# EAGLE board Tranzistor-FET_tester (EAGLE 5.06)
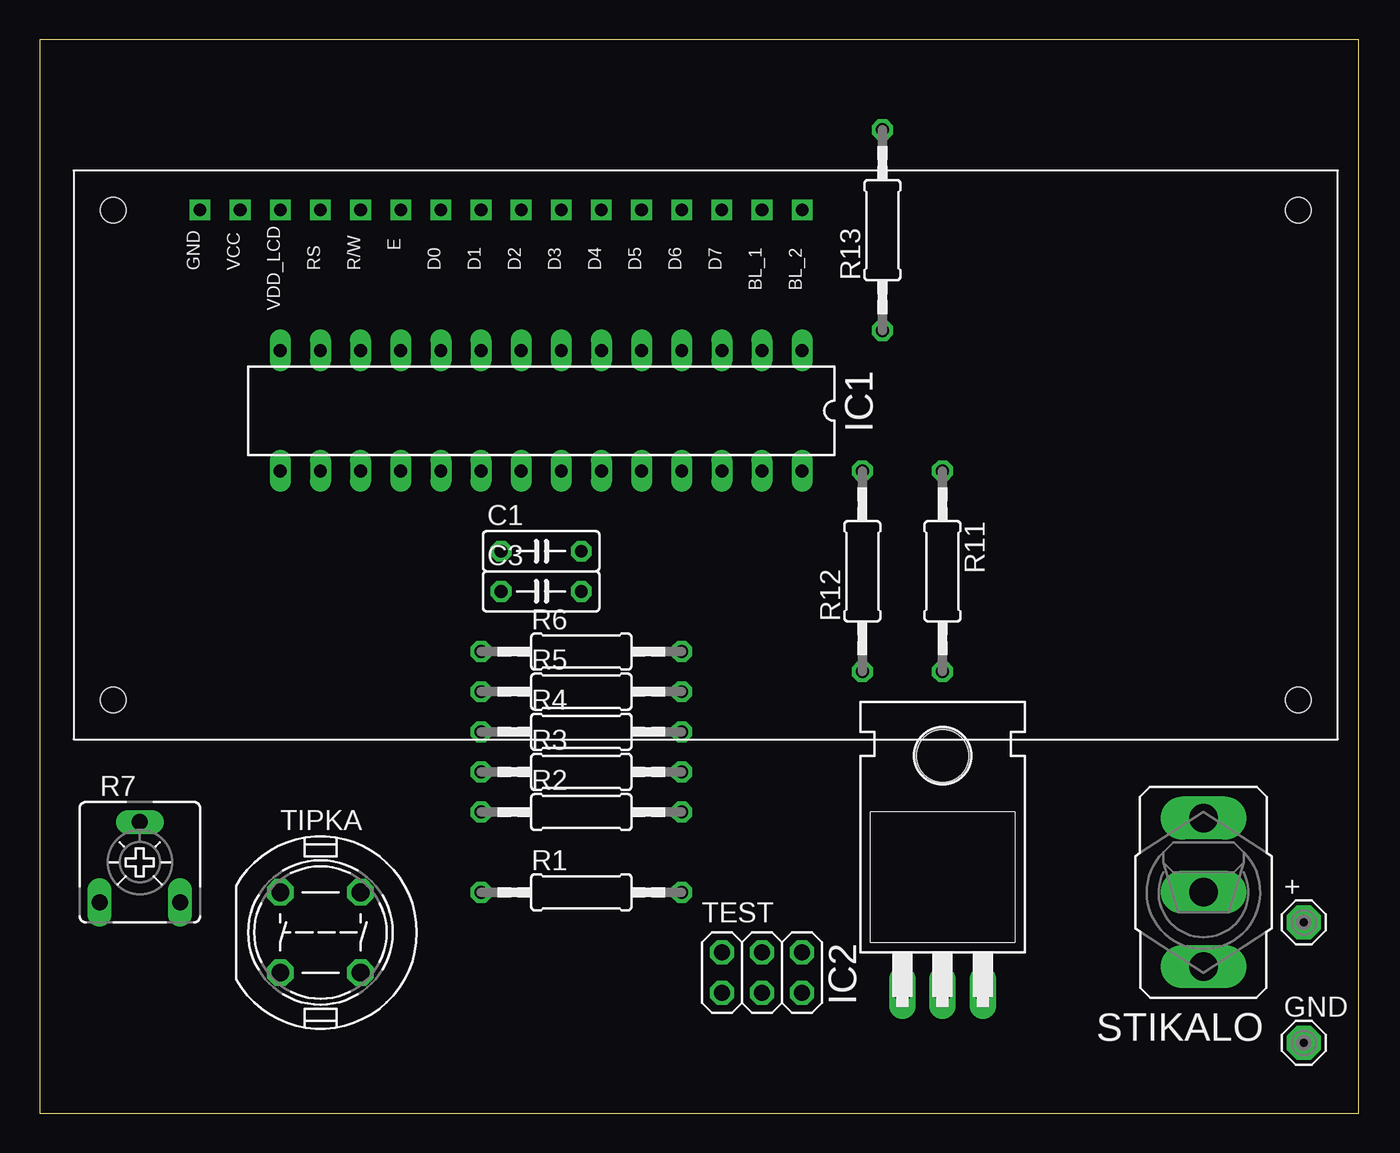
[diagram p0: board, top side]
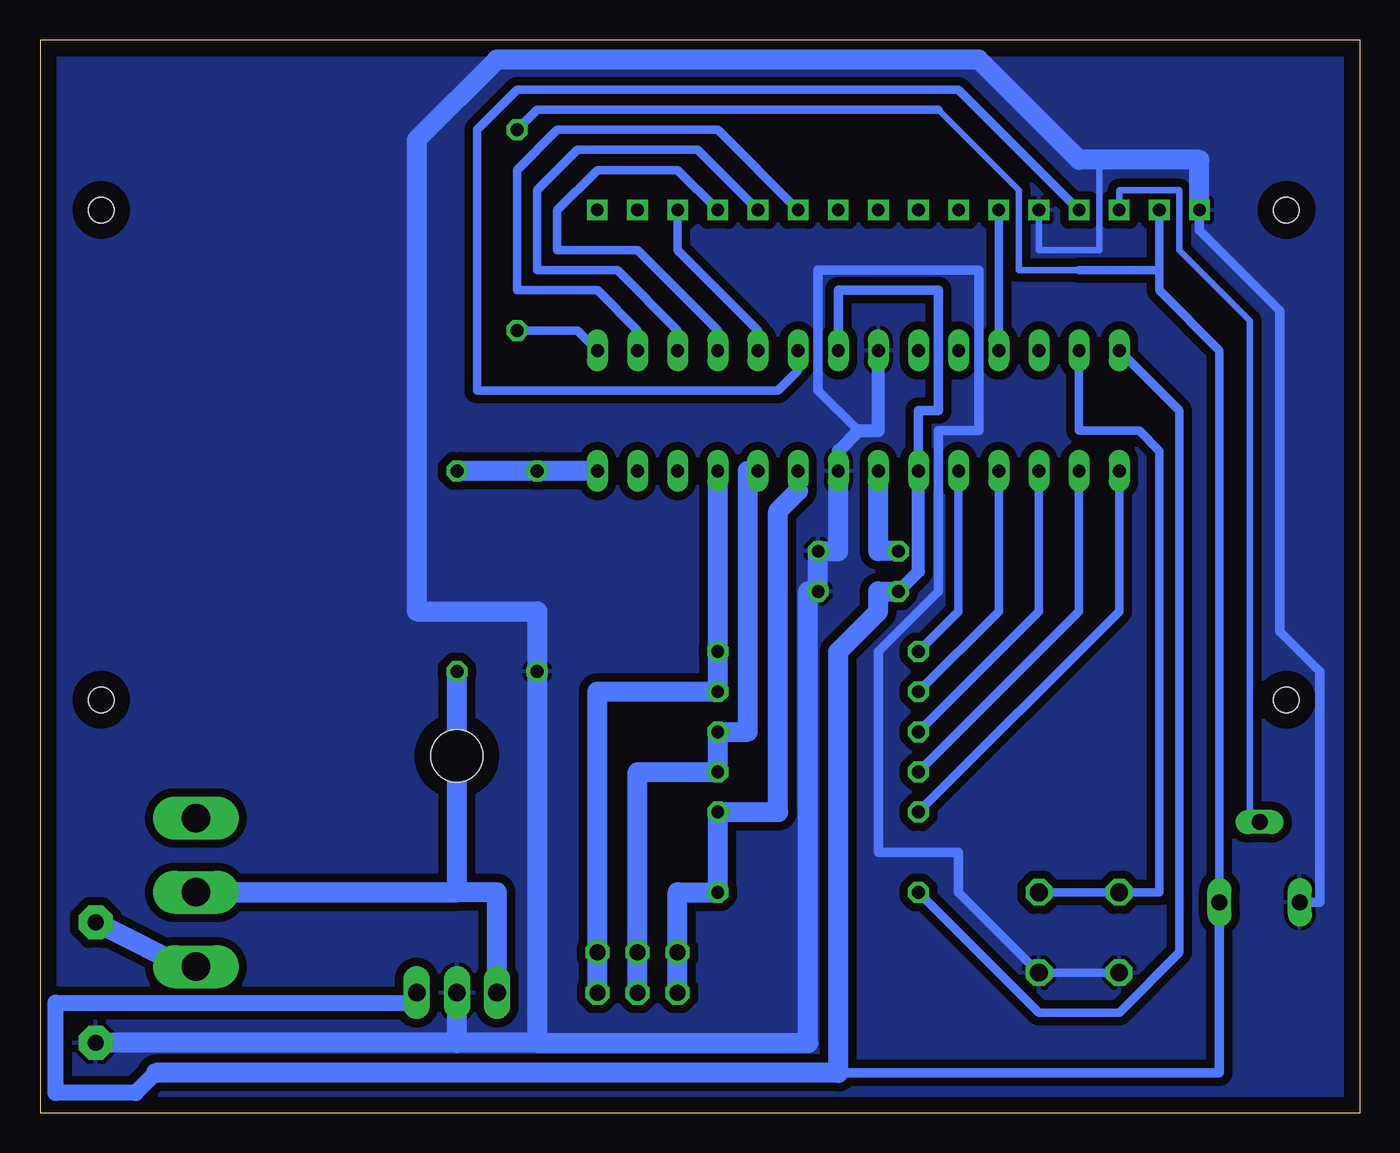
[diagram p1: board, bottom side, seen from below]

Size 83.49 x 67.94 mm. Coordinates in mm from the lower left corner, seen from the top.
Outline: 0,0 83.49,0 83.49,67.94 0,67.94 0,0
Copper layers (1*16): Top 0.035mm / dielectric 1.5mm / Bottom 0.035mm
Design rules "default *": minimum track width 21mil, minimum drill 24mil, track to track 21mil, track to pad 21mil, pad to pad 21mil, via to via 8mil, smd to smd 8mil, copper to edge 40mil, drill to drill 8mil, minimum pad ring 10mil, minimum via ring 8mil, stop-mask expansion 4mil, vias tented up to drill 0mil, thermal gap 10mil

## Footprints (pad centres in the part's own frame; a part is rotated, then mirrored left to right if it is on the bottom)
MCS10B = drill 1.016 pad 2.159 octagon: MP 0,0
C050-025X075 = drill 0.813 octagon: 1 -2.54,0; 2 2.54,0
DIL28-3 = drill 0.813 long: 1 -16.51,-3.81; 2 -13.97,-3.81; 3 -11.43,-3.81; 4 -8.89,-3.81; 5 -6.35,-3.81; 6 -3.81,-3.81; 7 -1.27,-3.81; 8 1.27,-3.81; 9 3.81,-3.81; 10 6.35,-3.81; 11 8.89,-3.81; 12 11.43,-3.81; 13 13.97,-3.81; 14 16.51,-3.81; 15 16.51,3.81; 16 13.97,3.81; 17 11.43,3.81; 18 8.89,3.81; 19 6.35,3.81; 20 3.81,3.81; 21 1.27,3.81; 22 -1.27,3.81; 23 -3.81,3.81; 24 -6.35,3.81; 25 -8.89,3.81; 26 -11.43,3.81; 27 -13.97,3.81; 28 -16.51,3.81
TO220H = drill 1.118 long: 1 -2.54,-10.16; 2 0,-10.16; 3 2.54,-10.16 | hole 3.302: 0,4.826
0207/12 = drill 0.813 octagon: 1 -6.35,0; 2 6.35,0
CA6V = drill 1.016 long: A -2.54,-2.54; E 2.54,-2.54; S 0,2.54
M9040P = drill 1.803 long: 1 0,4.699; 2 0,0; 3 0,-4.699
2X03 = drill 1.016 octagon: 1 -2.54,-1.27; 2 -2.54,1.27; 3 0,-1.27; 4 0,1.27; 5 2.54,-1.27; 6 2.54,1.27
DT6 = drill 1.118 octagon: 1 -2.54,2.54; 2 2.54,2.54; 3 2.54,-2.54; 4 -2.54,-2.54
DEM16216 = drill 0.8 square: BL_1 35.56,0; BL_2 38.1,0; D0 15.24,0; D1 17.78,0; D2 20.32,0; D3 22.86,0; D4 25.4,0; D5 27.94,0; D6 30.48,0; D7 33.02,0; E 12.7,0; GND 0,0; R/W 10.16,0; RS 7.62,0; VCC 2.54,0; VDD_LCD 5.08,0 | hole 1.6: -5.5,0; 69.5,0; -5.5,-31; 69.5,-31

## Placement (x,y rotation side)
+  MCS10B  [MCS10B]  80.01,12.07 0 top
C1  100n  [C050-025X075]  31.75,35.56 0 top
C3  100n  [C050-025X075]  31.75,33.02 0 top
GND  MCS10B  [MCS10B]  80.01,4.45 0 top
IC1  MEGA8-P  [DIL28-3]  31.75,44.45 180 top
IC2  7805T  [TO220H]  57.15,17.78 0 top
R1  680  [0207/12]  34.29,13.97 0 top
R2  470K  [0207/12]  34.29,19.05 0 top
R3  680  [0207/12]  34.29,21.59 0 top
R4  470K  [0207/12]  34.29,24.13 0 top
R5  680  [0207/12]  34.29,26.67 0 top
R6  470K  [0207/12]  34.29,29.21 0 top
R7  5K  [CA6V]  6.35,15.88 0 top
R11  10K  [0207/12]  57.15,34.29 270 top
R12  3K3  [0207/12]  52.07,34.29 90 top
R13  10K  [0207/12]  53.34,55.88 90 top
STIKALO  9450-1  [M9040P]  73.66,13.97 180 top
TEST  [2X03]  45.72,8.89 0 top
TIPKA  DT6  [DT6]  17.78,11.43 0 top
U$1  [DEM16216]  10.16,57.15 0 top

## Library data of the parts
+ GND = solpad
C1 C3 R1-R6 R11-R13 = rcl
IC1 = atmel
IC2 = linear
R7 = pot
STIKALO = switch
TEST = pinhead
TIPKA = switch-misc
U$1 = lcd

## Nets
+5V: R7.E R13.2 U$1.VCC
+9V: +.MP STIKALO.1
GND: C1.2 C3.2 GND.MP IC1.8 IC1.22 IC2.2 R7.A R12.1 TIPKA.3 TIPKA.4 U$1.GND U$1.R/W
N$1: IC1.23 R1.2 R2.2 TEST.1 TEST.2
N$2: IC1.24 R3.2 R4.2 TEST.3 TEST.4
N$3: IC1.25 R5.2 R6.2 TEST.5 TEST.6
N$4: IC1.13 TIPKA.1 TIPKA.2
N$6: R7.S U$1.VDD_LCD
N$7: IC1.28 R11.1 R12.2
N$9: IC1.14 R1.1
N$10: IC1.15 R2.1
N$11: IC1.16 R3.1
N$12: IC1.17 R4.1
N$13: IC1.18 R5.1
N$14: IC1.19 R6.1
N$15: IC1.1 R13.1
N$17: C1.1 IC1.21
N$18: C3.1 IC1.7 IC1.20 IC2.3
N$23: IC2.1 R11.2 STIKALO.2
N$24: IC1.2 U$1.D4
N$25: IC1.3 U$1.D5
N$26: IC1.4 U$1.D6
N$27: IC1.5 U$1.D7
N$28: IC1.6 U$1.RS
N$29: IC1.11 U$1.E

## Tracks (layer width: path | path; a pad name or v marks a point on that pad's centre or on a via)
+5V
  Bottom 0.406: 17.78,53.34 21.59,53.34 21.59,58.42 26.67,63.5
  Bottom 0.533: 12.7,53.34 17.78,53.34 | R13.2 52.07,63.5 26.67,63.5 | 12.7,53.34 12.7,52.07 8.89,48.26 R7.E | 12.7,53.34 U$1.VCC
+9V
  Bottom 0.533: STIKALO.1 73.66,8.89
  Bottom 1.27: 73.66,8.89 +.MP
GND
  Bottom 0.406: U$1.R/W 20.32,54.61 16.51,54.61 16.51,60.33
  Bottom 0.533: IC1.22 33.02,41.91 | TIPKA.3 TIPKA.4
  Bottom 0.61: TIPKA.3 25.4,13.97 25.4,16.51 30.48,16.51 30.48,29.21 26.67,33.02 26.67,43.18 24.13,43.18 24.13,53.34 34.29,53.34 34.29,45.72 31.75,43.18 | U$1.GND 10.16,55.88 5.08,50.8 5.08,30.48 2.54,27.94 2.54,13.34 R7.A
  Bottom 0.813: IC1.8 30.48,43.18 31.75,43.18 33.02,41.91 | 34.92,33.02 C3.2
  Bottom 1.27: U$1.GND 10.16,60.33 16.51,60.33 17.78,60.33 24.13,66.67 54.61,66.67 59.69,61.59 59.69,31.75 52.07,31.75 R12.1 52.07,4.45 | C3.2 C1.2 33.02,35.56 IC1.22 | 34.92,33.02 34.92,4.45 52.07,4.45 | 52.07,4.45 57.15,4.45 | 57.15,4.45 GND.MP | 57.15,4.45 IC2.2
  pour Bottom: 0,67.31 83.82,67.31 83.82,0 0,0 0,1.27
N$1
  Bottom 0.533: 35.56,39.37 IC1.23
  Bottom 1.27: TEST.1 TEST.2 43.18,13.97 R1.2 R2.2 36.83,19.05 36.83,38.1 35.56,39.37
N$2
  Bottom 0.813: 38.73,40.64 IC1.24
  Bottom 1.27: TEST.3 TEST.4 45.72,21.59 R3.2 R4.2 38.73,24.13 38.73,36.83 38.73,40.64
N$3
  Bottom 1.27: TEST.5 TEST.6 48.26,26.67 R5.2 R6.2 IC1.25
N$4
  Bottom 0.533: IC1.13 17.78,43.18 13.97,43.18 12.7,41.91 12.7,13.97 TIPKA.2 TIPKA.1
N$6
  Bottom 0.406: U$1.VDD_LCD 15.24,58.42 11.43,58.42 11.43,54.61 6.99,50.17 6.99,18.41 R7.S
N$7
  Bottom 1.27: IC1.28 R12.2 R11.1
N$9
  Bottom 0.533: R1.1 20.32,6.35 15.24,6.35 11.43,10.16 11.43,44.45 IC1.14
N$10
  Bottom 0.533: R2.1 15.24,31.75 IC1.15
N$11
  Bottom 0.533: R3.1 17.78,31.75 IC1.16
N$12
  Bottom 0.533: R4.1 20.32,31.75 IC1.17
N$13
  Bottom 0.533: R5.1 22.86,31.75 IC1.18
N$14
  Bottom 0.533: R6.1 25.4,31.75 IC1.19
N$15
  Bottom 0.533: IC1.1 49.53,49.53 R13.1
N$17
  Bottom 1.27: C1.1 30.48,35.56 IC1.21
N$18
  Bottom 0.61: IC1.7 33.02,52.07 26.67,52.07 26.67,44.45 27.94,44.45 IC1.20 | 8.89,12.7 8.89,2.54 33.02,2.54
  Bottom 0.813: IC1.20 27.94,34.29 C3.1
  Bottom 1.016: 76.2,2.54 77.47,1.27 82.55,1.27 82.55,6.98 59.69,6.98
  Bottom 1.27: C3.1 30.48,33.02 30.48,31.75 33.02,29.21 33.02,2.54 76.2,2.54 | 59.69,6.98 IC2.3
N$23
  Bottom 1.27: R11.2 57.15,13.97 72.39,13.97 | 72.39,13.97 STIKALO.2 | 72.39,13.97 54.61,13.97 IC2.1
N$24
  Bottom 0.533: U$1.D4 40.64,62.23 50.8,62.23 53.34,59.69 53.34,52.07 48.26,52.07 45.72,49.53 IC1.2
N$25
  Bottom 0.533: U$1.D5 41.91,60.96 49.53,60.96 52.07,58.42 52.07,53.34 46.99,53.34 43.18,49.53 IC1.3
N$26
  Bottom 0.533: U$1.D6 43.18,59.69 48.26,59.69 50.8,57.15 50.8,54.61 45.72,54.61 40.64,49.53 IC1.4
N$27
  Bottom 0.533: U$1.D7 43.18,54.61 38.1,49.53 IC1.5
N$28
  Bottom 0.533: U$1.RS 25.4,64.77 53.34,64.77 55.88,62.23 55.88,45.72 36.83,45.72 35.56,46.99 IC1.6
N$29
  Bottom 0.533: IC1.11 U$1.E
